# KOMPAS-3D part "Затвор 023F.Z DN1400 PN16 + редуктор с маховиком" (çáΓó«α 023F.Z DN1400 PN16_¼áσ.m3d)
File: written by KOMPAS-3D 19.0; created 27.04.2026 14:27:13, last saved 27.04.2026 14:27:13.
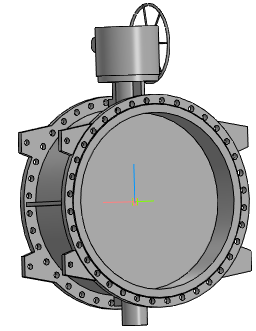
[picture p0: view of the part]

Document properties: Полное имя файла: ..\..\Затвор 023F.Z DN200-DN1600_с маховиком\Затвор 023F.Z DN1400 PN16 + редуктор с маховиком.a3d

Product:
- Part/product: Затвор 023F.Z DN1400 PN16 + редуктор с маховиком
    Масса: 3565.33

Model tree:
1. Операция без истории:1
